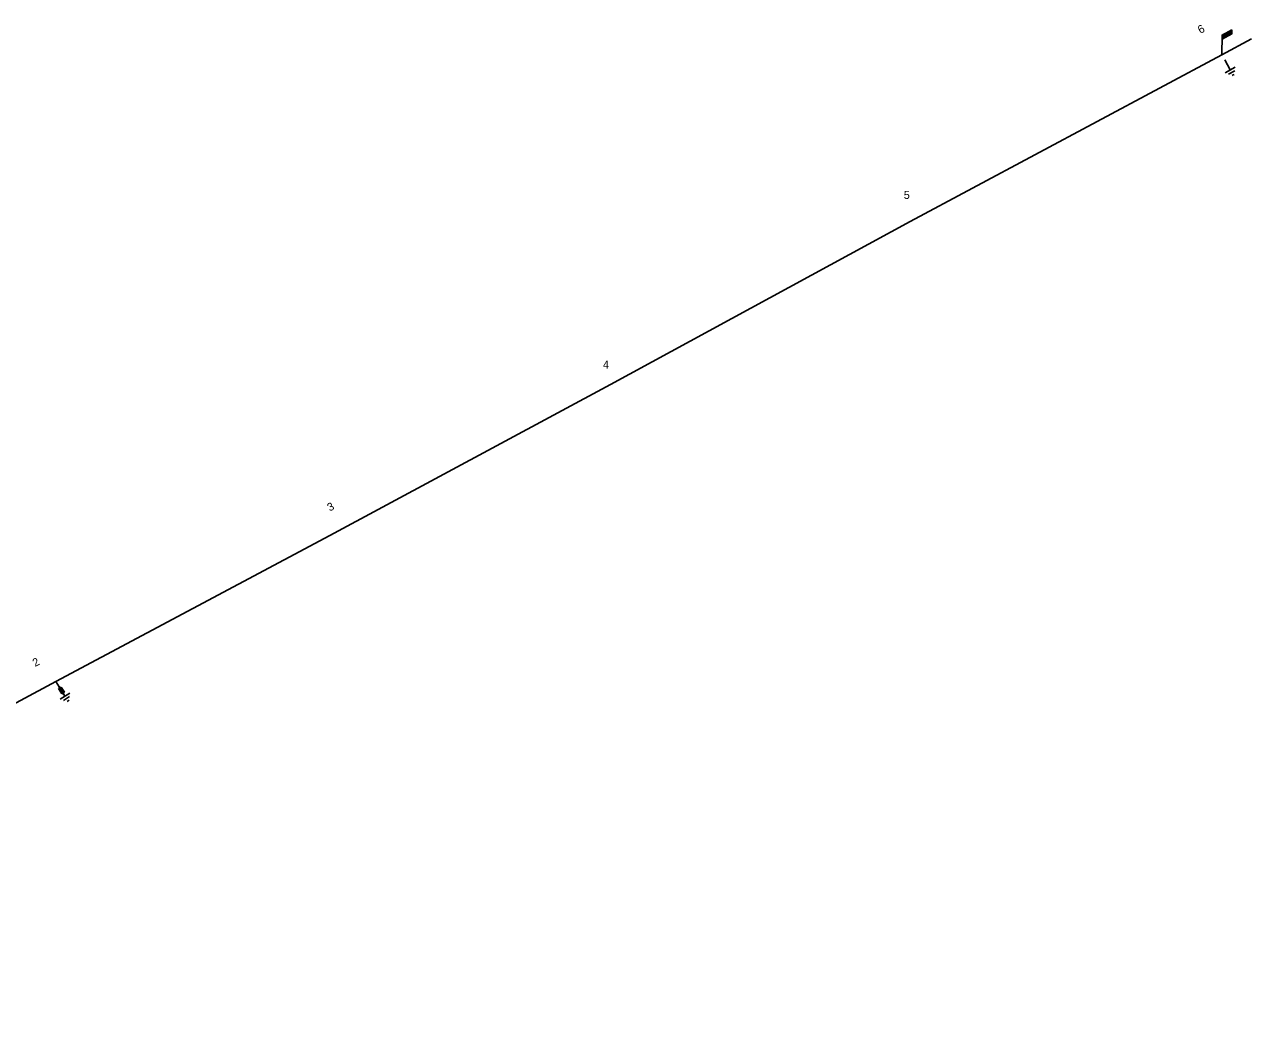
# Model space of a CAD drawing. Extents: x -762500 to -761250, y -1153000 to -1152000.
# Drawn here: x -761516.7 to -761250, y -1152903 to -1152687.7 of the extents above; entities that cross this region are included whole.
import ezdxf

# ---------------------------------------------------------------- set-up
doc = ezdxf.new("R2010")
doc.units = 0
for name, color, linetype in [('Vrstva 11', 7, 'Continuous'), ('Vrstva 14', 7, 'Continuous'), ('Vrstva 15', 7, 'Continuous'), ('Vrstva 16', 7, 'Continuous'), ('Vrstva 4', 7, 'Continuous')]:
    doc.layers.add(name, color=color, linetype=linetype)

msp = doc.modelspace()

# ---------------------------------------------------------------- linework, layer by layer
at = {"layer": 'Vrstva 11'}
for p, q in [((-761256.385, -1152690.84), (-761254.276, -1152689.67)), ((-761256.384, -1152690.725), (-761254.274, -1152689.555)), ((-761256.384, -1152690.782), (-761254.275, -1152689.613)), ((-761256.383, -1152690.667), (-761254.273, -1152689.497)), ((-761256.382, -1152690.609), (-761254.272, -1152689.44)), ((-761256.381, -1152690.494), (-761254.27, -1152689.324)), ((-761256.381, -1152690.552), (-761254.271, -1152689.382)), ((-761256.38, -1152690.437), (-761254.269, -1152689.266)), ((-761256.379, -1152690.379), (-761254.268, -1152689.209)), ((-761256.378, -1152690.264), (-761254.266, -1152689.093)), ((-761256.378, -1152690.322), (-761254.267, -1152689.151)), ((-761256.377, -1152690.206), (-761254.265, -1152689.035)), ((-761256.376, -1152690.091), (-761254.263, -1152688.92)), ((-761256.376, -1152690.149), (-761254.264, -1152688.978)), ((-761256.375, -1152690.034), (-761256.015, -1152689.834))]:
    msp.add_line(p, q, dxfattribs=at)
msp.add_lwpolyline([(-761256.375, -1152690.033), (-761256.43, -1152694.33)], dxfattribs=at)
msp.add_lwpolyline([(-761254.262, -1152688.867), (-761256.375, -1152690.033), (-761256.386, -1152690.894), (-761254.276, -1152689.724)], close=True, dxfattribs=at)
at = {"layer": 'Vrstva 15'}
for points in [[(-761255.822, -1152695.419), (-761254.61, -1152697.606)], [(-761253.517, -1152697), (-761255.704, -1152698.212)], [(-761253.638, -1152697.776), (-761255.016, -1152698.54)], [(-761254.004, -1152698.699), (-761254.228, -1152698.823)], [(-761253.772, -1152698.57), (-761254.004, -1152698.699)], [(-761509.266, -1152831.625), (-761507.942, -1152833.746)], [(-761506.881, -1152833.083), (-761509.002, -1152834.408)], [(-761506.962, -1152833.865), (-761508.297, -1152834.699)], [(-761507.279, -1152834.806), (-761507.496, -1152834.941)], [(-761507.054, -1152834.665), (-761507.279, -1152834.806)]]:
    msp.add_lwpolyline(points, dxfattribs=at)
at = {"layer": 'Vrstva 16'}
for points in [[(-761509.929, -1152830.567), (-761508.812, -1152832.353)], [(-761509.338, -1152832.124), (-761508.779, -1152831.775)], [(-761508.639, -1152833.243), (-761509.338, -1152832.124)], [(-761508.812, -1152832.353), (-761509.043, -1152832.207)], [(-761508.812, -1152832.353), (-761508.843, -1152832.082)], [(-761508.779, -1152831.775), (-761508.08, -1152832.894)], [(-761508.08, -1152832.894), (-761508.639, -1152833.243)], [(-761508.364, -1152833.071), (-761507.941, -1152833.747)]]:
    msp.add_lwpolyline(points, dxfattribs=at)
at = {"layer": 'Vrstva 4'}
for points in [[(-761256.43, -1152694.33), (-761250, -1152690.82)], [(-761645.63, -1152902.98), (-761578.2, -1152867.28), (-761509.93, -1152830.57), (-761450.39, -1152798.8), (-761389.38, -1152766.03), (-761324.2, -1152730.53), (-761256.43, -1152694.33)]]:
    msp.add_lwpolyline(points, dxfattribs=at)

# ---------------------------------------------------------------- texts
at = {"layer": 'Vrstva 14'}
for s, p in [('6', (-761261.11, -1152689.78)), ('3', (-761450.37, -1152793.64)), ('2', (-761514.44, -1152827.43))]:
    msp.add_text(s, height=1.74, rotation=28, dxfattribs=at).set_placement(p)
for s, p in [('5', (-761325.58, -1152725.65)), ('4', (-761390.98, -1152762.53))]:
    msp.add_text(s, height=1.74, dxfattribs=at).set_placement(p)

doc.saveas('drawing.dxf')
